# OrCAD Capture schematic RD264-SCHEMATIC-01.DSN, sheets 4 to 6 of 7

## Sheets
4 4: size A3
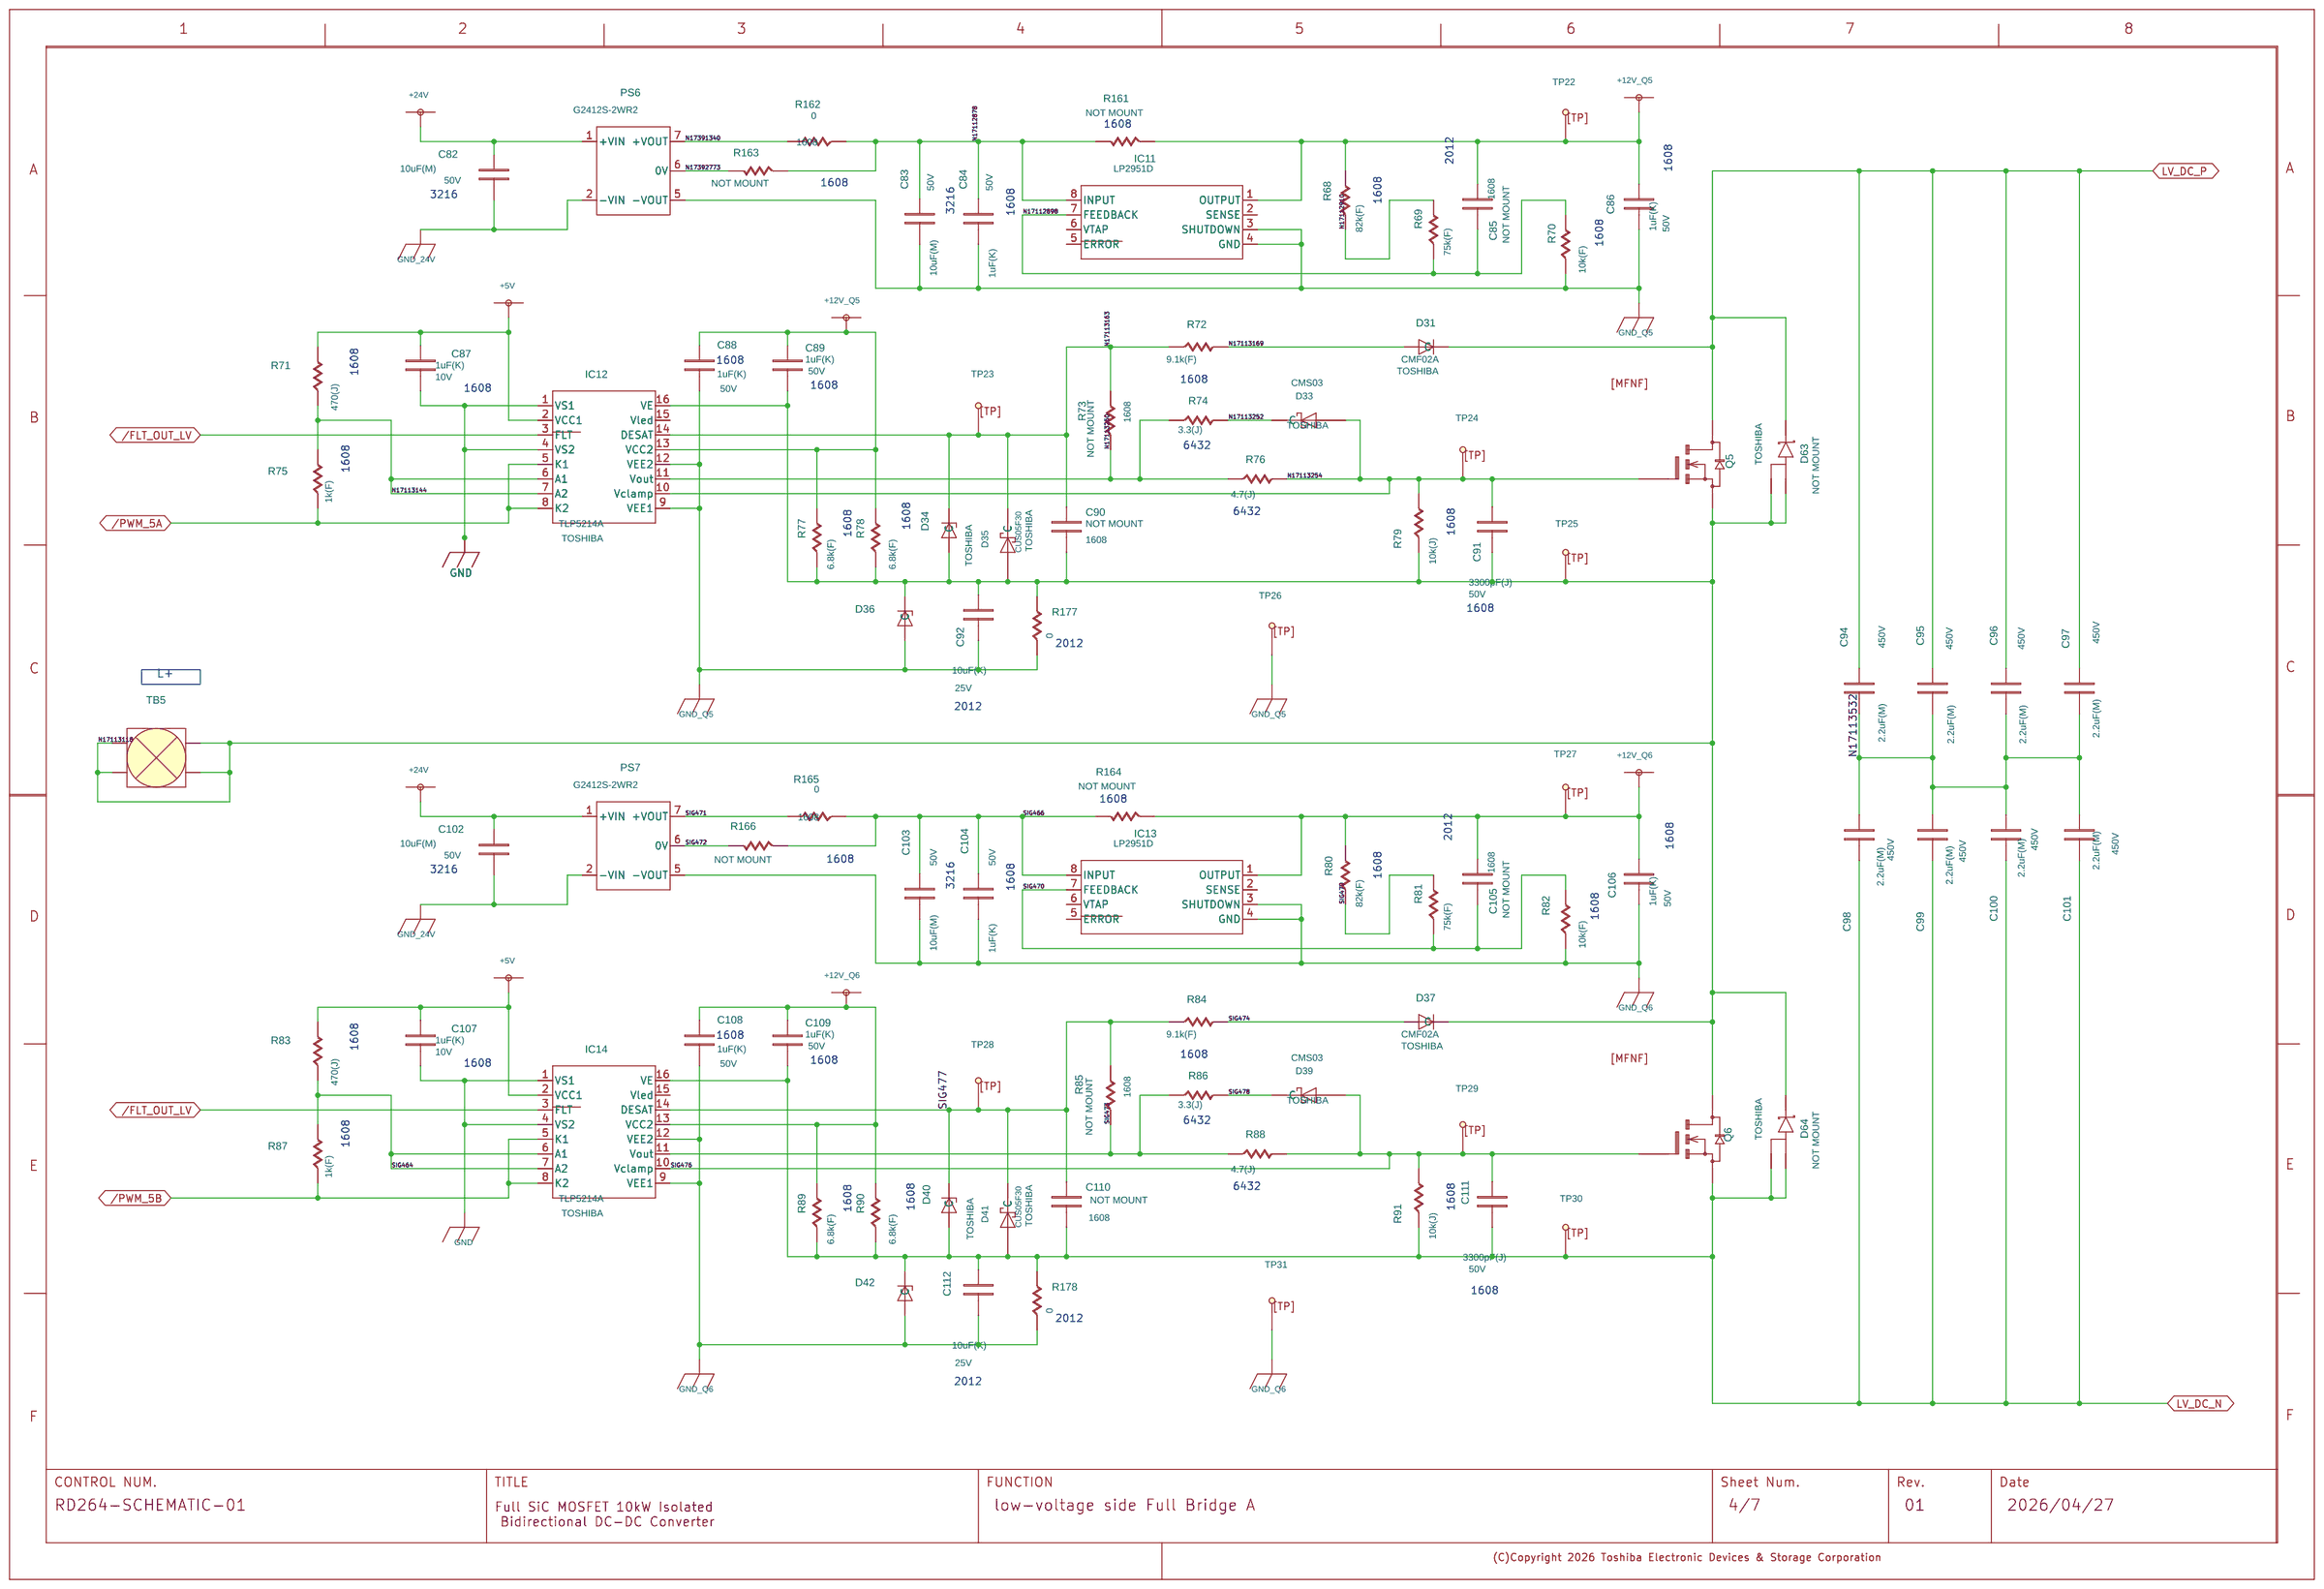
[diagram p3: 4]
5 3: size A3
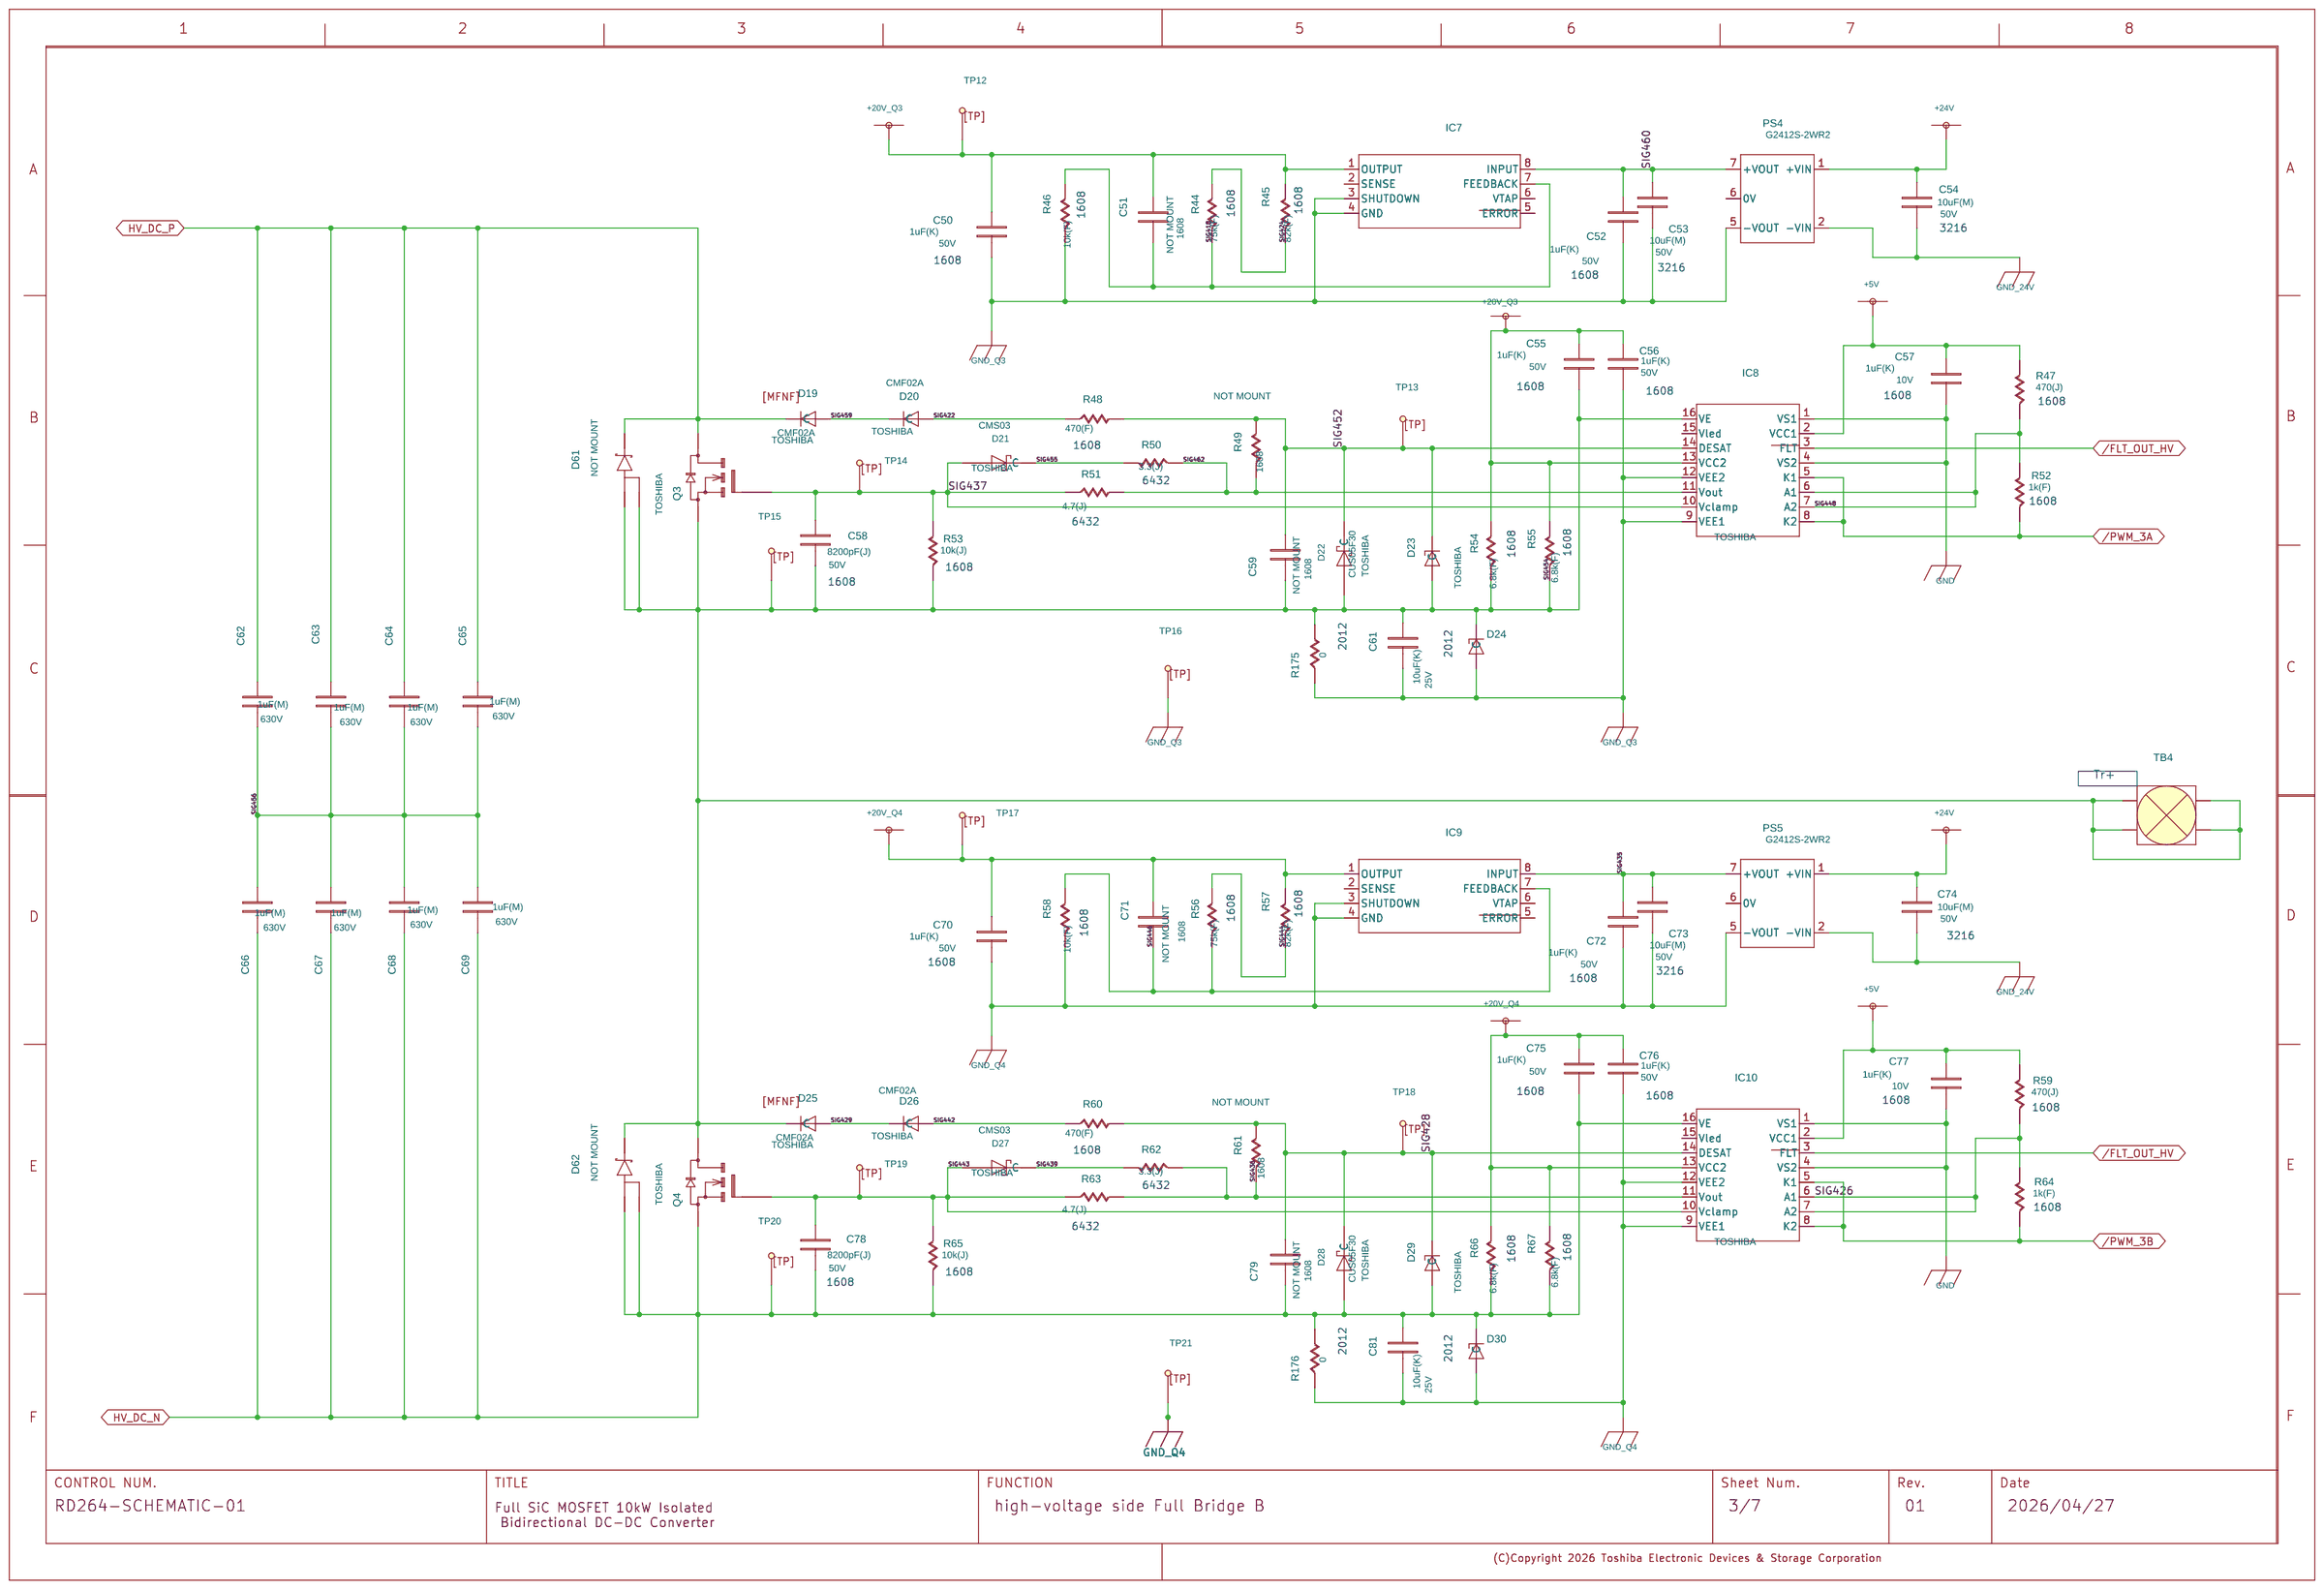
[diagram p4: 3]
6 2: size A3
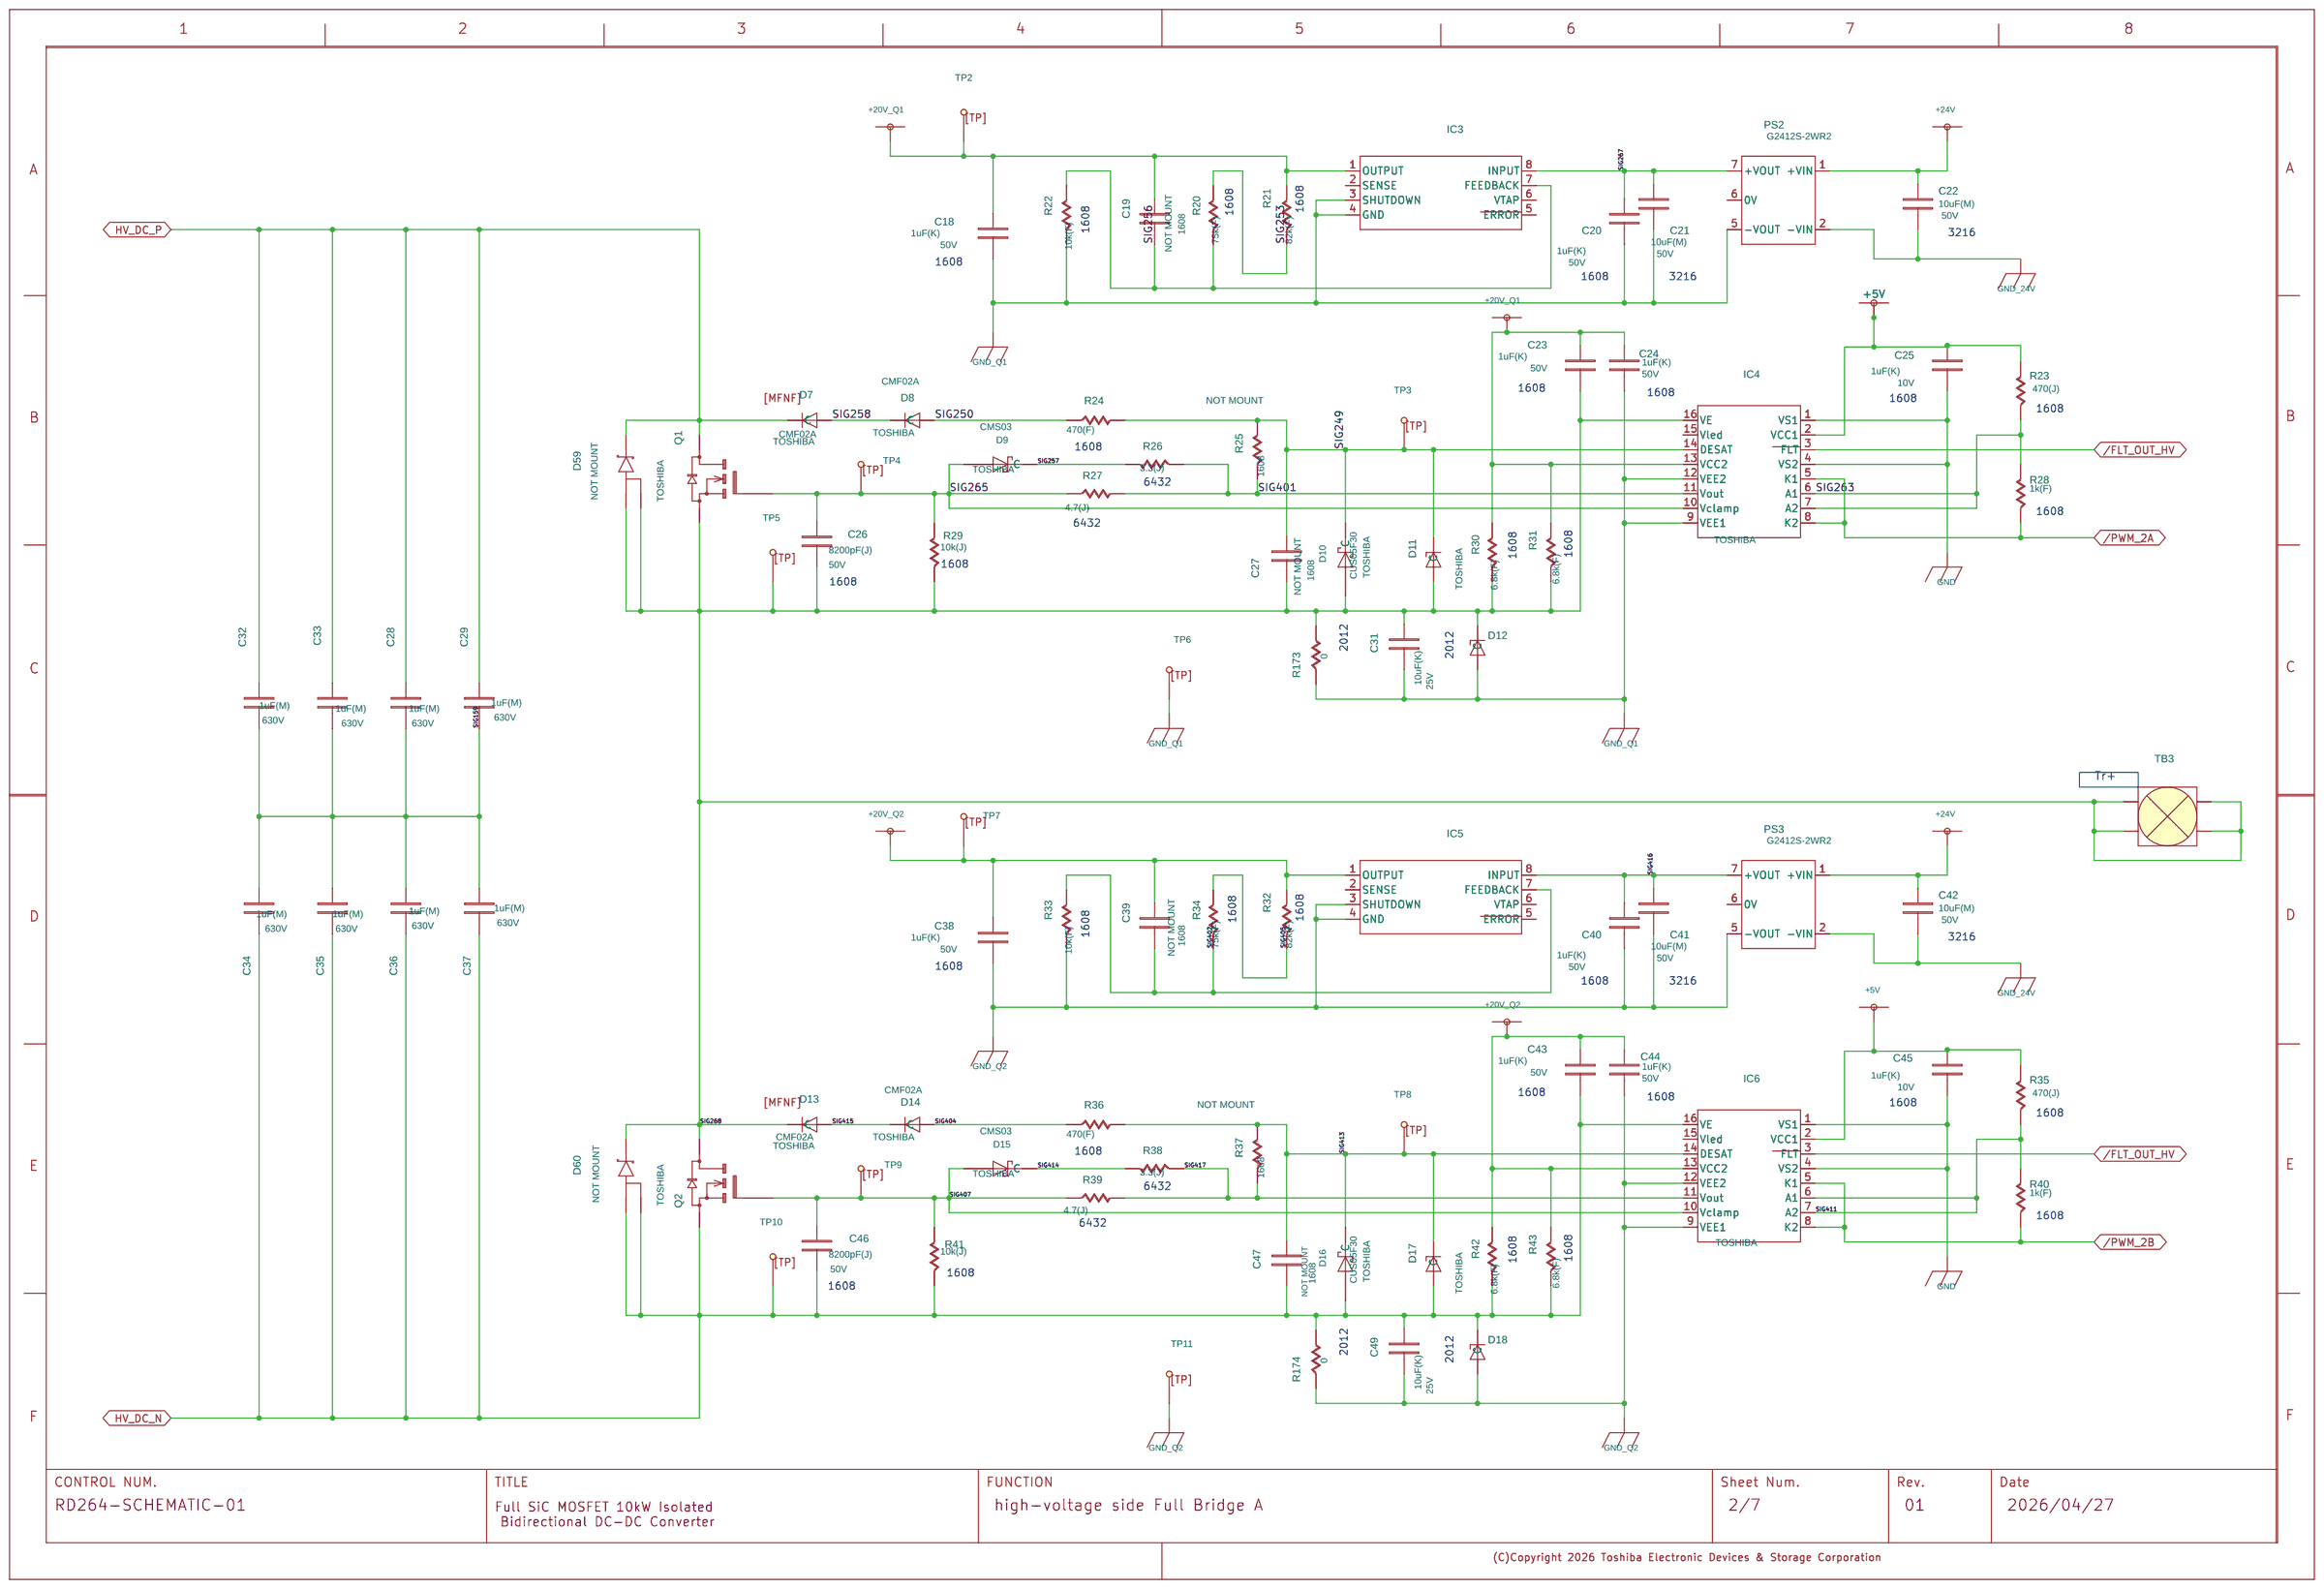
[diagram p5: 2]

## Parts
sheet 2
C18  GRM188R61H105KAALD
C19  NC_C1608
C20  GRM188R61H105KAALD
C21  GRM31CR61H106MA12L
C22  GRM31CR61H106MA12L
C23  GRM188R61H105KAALD
C24  GRM188R61H105KAALD
C25  GRM188R71A105KA61D
C26  GRM1885C1H332JA01D
C27  NC_C1608
C28  CKG57NX7T2J105M500JH
C29  CKG57NX7T2J105M500JH
C31  GRM21BC71E106KE11L
C32  CKG57NX7T2J105M500JH
C33  CKG57NX7T2J105M500JH
C34  CKG57NX7T2J105M500JH
C35  CKG57NX7T2J105M500JH
C36  CKG57NX7T2J105M500JH
C37  CKG57NX7T2J105M500JH
C38  GRM188R61H105KAALD
C39  NC_C1608
C40  GRM188R61H105KAALD
C41  GRM31CR61H106MA12L
C42  GRM31CR61H106MA12L
C43  GRM188R61H105KAALD
C44  GRM188R61H105KAALD
C45  GRM188R71A105KA61D
C46  GRM1885C1H332JA01D
C47  NC_C1608
C49  GRM21BC71E106KE11L
D7  CMF05
D8  CMF05
D9  SBD
D10  SBD
D11  CRY82
D12  KDZVTR2.0B
D13  CMF05
D14  CMF05
D15  SBD
D16  SBD
D17  CRY82
D18  KDZVTR2.0B
D59  NC_TO-247
D60  NC_TO-247
IC3  LP2951D
IC4  TLP5214A
IC5  LP2951D
IC6  TLP5214A
PS2  G2412S-2WR2
PS3  G2412S-2WR2
Q1  TW070J120B
Q2  TW070J120B
R20  RK73H1JTTD7502F
R21  RK73H1JTTD8202F
R22  RK73H1JTTD1002F
R23  RK73B1JTTD471J
R24  ERJ3EKF4700V
R25  NC_R1608
R26  ERJ1TYJ3R3U
R27  ERJ1TYJ4R7U
R28  RK73H1JTTD1001F
R29  RK73B1JTTD103J
R30  RK73H1JTTD6801F
R31  RK73H1JTTD6801F
R32  RK73H1JTTD8202F
R33  RK73H1JTTD1002F
R34  RK73H1JTTD7502F
R35  RK73B1JTTD471J
R36  ERJ3EKF4700V
R37  NC_R1608
R38  ERJ1TYJ3R3U
R39  ERJ1TYJ4R7U
R40  RK73H1JTTD1001F
R41  RK73B1JTTD103J
R42  RK73H1JTTD6801F
R43  RK73H1JTTD6801F
R173  RK73Z2ATTD
R174  RK73Z2ATTD
TB3  OP-057
TP2  TP
TP3  TP
TP4  TP
TP5  TP
TP6  TP
TP7  TP
TP8  TP
TP9  TP
TP10  TP
TP11  TP
U?#5  WAKU_DEF100
sheet 3
C50  GRM188R61H105KAALD
C51  NC_C1608
C52  GRM188R61H105KAALD
C53  GRM31CR61H106MA12L
C54  GRM31CR61H106MA12L
C55  GRM188R61H105KAALD
C56  GRM188R61H105KAALD
C57  GRM188R71A105KA61D
C58  GRM1885C1H332JA01D
C59  NC_C1608
C61  GRM21BC71E106KE11L
C62  CKG57NX7T2J105M500JH
C63  CKG57NX7T2J105M500JH
C64  CKG57NX7T2J105M500JH
C65  CKG57NX7T2J105M500JH
C66  CKG57NX7T2J105M500JH
C67  CKG57NX7T2J105M500JH
C68  CKG57NX7T2J105M500JH
C69  CKG57NX7T2J105M500JH
C70  GRM188R61H105KAALD
C71  NC_C1608
C72  GRM188R61H105KAALD
C73  GRM31CR61H106MA12L
C74  GRM31CR61H106MA12L
C75  GRM188R61H105KAALD
C76  GRM188R61H105KAALD
C77  GRM188R71A105KA61D
C78  GRM1885C1H332JA01D
C79  NC_C1608
C81  GRM21BC71E106KE11L
D19  CMF05
D20  CMF05
D21  SBD
D22  SBD
D23  CRY82
D24  KDZVTR2.0B
D25  CMF05
D26  CMF05
D27  SBD
D28  SBD
D29  CRY82
D30  KDZVTR2.0B
D61  NC_TO-247
D62  NC_TO-247
IC7  LP2951D
IC8  TLP5214A
IC9  LP2951D
IC10  TLP5214A
PS4  G2412S-2WR2
PS5  G2412S-2WR2
Q3  TW070J120B
Q4  TW070J120B
R44  RK73H1JTTD7502F
R45  RK73H1JTTD8202F
R46  RK73H1JTTD1002F
R47  RK73B1JTTD471J
R48  ERJ3EKF4700V
R49  NC_R1608
R50  ERJ1TYJ3R3U
R51  ERJ1TYJ4R7U
R52  RK73H1JTTD1001F
R53  RK73B1JTTD103J
R54  RK73H1JTTD6801F
R55  RK73H1JTTD6801F
R56  RK73H1JTTD7502F
R57  RK73H1JTTD8202F
R58  RK73H1JTTD1002F
R59  RK73B1JTTD471J
R60  ERJ3EKF4700V
R61  NC_R1608
R62  ERJ1TYJ3R3U
R63  ERJ1TYJ4R7U
R64  RK73H1JTTD1001F
R65  RK73B1JTTD103J
R66  RK73H1JTTD6801F
R67  RK73H1JTTD6801F
R175  RK73Z2ATTD
R176  RK73Z2ATTD
TB4  OP-057
TP12  TP
TP13  TP
TP14  TP
TP15  TP
TP16  TP
TP17  TP
TP18  TP
TP19  TP
TP20  TP
TP21  TP
U?#4  WAKU_DEF100
sheet 4
C82  GRM31CR61H106MA12L
C83  GRM31CR61H106MA12L
C84  GRM188R61H105KAALD
C85  NC_C1608
C86  GRM188R61H105KAALD
C87  GRM188R71A105KA61D
C88  GRM188R61H105KAALD
C89  GRM188R61H105KAALD
C90  NC_C1608
C91  GRM1885C1H682JA01D
C92  GRM21BC71E106KE11L
C94  CKG57NX7T2W225M500JH
C95  CKG57NX7T2W225M500JH
C96  CKG57NX7T2W225M500JH
C97  CKG57NX7T2W225M500JH
C98  CKG57NX7T2W225M500JH
C99  CKG57NX7T2W225M500JH
C100  CKG57NX7T2W225M500JH
C101  CKG57NX7T2W225M500JH
C102  GRM31CR61H106MA12L
C103  GRM31CR61H106MA12L
C104  GRM188R61H105KAALD
C105  NC_C1608
C106  GRM188R61H105KAALD
C107  GRM188R71A105KA61D
C108  GRM188R61H105KAALD
C109  GRM188R61H105KAALD
C110  NC_C1608
C111  GRM1885C1H682JA01D
C112  GRM21BC71E106KE11L
D31  CMF05
D33  SBD
D34  CRY82
D35  SBD
D36  KDZVTR2.0B
D37  CMF05
D39  SBD
D40  CRY82
D41  SBD
D42  KDZVTR2.0B
D63  NC_TO-247
D64  NC_TO-247
IC11  LP2951D
IC12  TLP5214A
IC13  LP2951D
IC14  TLP5214A
PS6  G2412S-2WR2
PS7  G2412S-2WR2
Q5  TK49N65W5
Q6  TK49N65W5
R68  RK73H1JTTD8202F
R69  RK73H1JTTD7502F
R70  RK73H1JTTD1002F
R71  RK73B1JTTD471J
R72  ERJ3EKF9101V
R73  NC_R1608
R74  ERJ1TYJ100U
R75  RK73H1JTTD1001F
R76  ERJ1TYJ470U
R77  RK73H1JTTD6801F
R78  RK73H1JTTD6801F
R79  RK73B1JTTD103J
R80  RK73H1JTTD8202F
R81  RK73H1JTTD7502F
R82  RK73H1JTTD1002F
R83  RK73B1JTTD471J
R84  ERJ3EKF9101V
R85  NC_R1608
R86  ERJ1TYJ100U
R87  RK73H1JTTD1001F
R88  ERJ1TYJ470U
R89  RK73H1JTTD6801F
R90  RK73H1JTTD6801F
R91  RK73B1JTTD103J
R161  RK73Z1JTTD
R162  NC_R1608
R163  RK73Z1JTTD
R164  RK73Z1JTTD
R165  NC_R1608
R166  RK73Z1JTTD
R177  RK73Z2ATTD
R178  RK73Z2ATTD
TB5  OP-057
TP22  TP
TP23  TP
TP24  TP
TP25  TP
TP26  TP
TP27  TP
TP28  TP
TP29  TP
TP30  TP
TP31  TP
U?#3  WAKU_DEF100

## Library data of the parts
C18 C38 C50 C70 = C_v2: COMP: C-GRM188R61H105KAALD; COMPONENTNAME: C_C.Normal_package; COMPONENTTYPE: 4; FUNCN: C_C.Normal_package; INSTANCENAME: INS16721371; NOTE: 1uF 50V; PART TYPE: Ceramic Capacitor; REFERENCE TEMPLATE: C; SIZE: 1; VAL1: 1uF(K); VAL2: 50V
C19 C39 C51 C71 = C_v2: COMP: C-1608_NM; COMPONENTNAME: C_C.Normal_package; COMPONENTTYPE: 4; FUNCN: C_C.Normal_package; INSTANCENAME: INS16721315; NOTMOUNT: NOT MOUNT; PART TYPE: Ceramic Capacitor; REFERENCE TEMPLATE: C; SIZE: 1; SIZECODESMD: 1608
C20 C40 C52 C72 = C_v2: COMP: C-GRM188R61H105KAALD; COMPONENTNAME: C_C.Normal_package; COMPONENTTYPE: 4; FUNCN: C_C.Normal_package; INSTANCENAME: INS15595921; NOTE: 1uF 50V; PART TYPE: Ceramic Capacitor; REFERENCE TEMPLATE: C; SIZE: 1; VAL1: 1uF(K); VAL2: 50V
C21 C41 C53 C73 = C_v2: COMP: C-GRM31CR61H106MA12L; COMPONENTNAME: C_C.Normal_package; COMPONENTTYPE: 4; FUNCN: C_C.Normal_package; INSTANCENAME: INS15595987; NOTE: 10uF 50V; PART TYPE: Ceramic Capacitor; REFERENCE TEMPLATE: C; SIZE: 1; VAL1: 10uF(M); VAL2: 50V
C22 C42 C54 C74 = C_v2: COMP: C-GRM31CR61H106MA12L; COMPONENTNAME: C_C.Normal_package; COMPONENTTYPE: 4; FUNCN: C_C.Normal_package; INSTANCENAME: INS15596097; NOTE: 10uF 50V; PART TYPE: Ceramic Capacitor; REFERENCE TEMPLATE: C; SIZE: 1; VAL1: 10uF(M); VAL2: 50V
C23 C43 C55 C75 = C_v2: COMP: C-GRM188R61H105KAALD; COMPONENTNAME: C_C.Normal_package; COMPONENTTYPE: 4; FUNCN: C_C.Normal_package; INSTANCENAME: INS15596075; NOTE: 1uF 50V; PART TYPE: Ceramic Capacitor; REFERENCE TEMPLATE: C; SIZE: 1; VAL1: 1uF(K); VAL2: 50V
C24 C44 C56 C76 = C_v2: COMP: C-GRM188R61H105KAALD; COMPONENTNAME: C_C.Normal_package; COMPONENTTYPE: 4; FUNCN: C_C.Normal_package; INSTANCENAME: INS15596185; NOTE: 1uF 50V; PART TYPE: Ceramic Capacitor; REFERENCE TEMPLATE: C; SIZE: 1; VAL1: 1uF(K); VAL2: 50V
C25 C45 C57 C77 = C_v2: COMP: C-GRM188R71A105KA61D; COMPONENTNAME: C_C.Normal_package; COMPONENTTYPE: 4; FUNCN: C_C.Normal_package; INSTANCENAME: INS15595789; NOTE: 1uF 10V; PART TYPE: Ceramic Capacitor; REFERENCE TEMPLATE: C; SIZE: 1; VAL1: 1uF(K); VAL2: 10V
C26 C46 C58 C78 = C_v2: COMP: C-GRM1885C1H332JA01D; COMPONENTNAME: C_C.Normal_package; COMPONENTTYPE: 4; FUNCN: C_C.Normal_package; INSTANCENAME: INS15595745; NOTE: 3300pF 50V; PART TYPE: Ceramic Capacitor; REFERENCE TEMPLATE: C; SIZE: 1; VAL1: 8200pF(J); VAL2: 50V
C27 C47 C59 C79 = C_v2: COMP: C-1608_NM; COMPONENTNAME: C_C.Normal_package; COMPONENTTYPE: 4; FUNCN: C_C.Normal_package; INSTANCENAME: INS15596281; NOTMOUNT: NOT MOUNT; PART TYPE: Ceramic Capacitor; REFERENCE TEMPLATE: C; SIZE: 1; SIZECODESMD: 1608
C28 C64 = C_v2: COMP: C-CKG57NX7T2J105M500JH; COMPONENTNAME: C_C.Normal_package; COMPONENTTYPE: 4; FUNCN: C_C.Normal_package; INSTANCENAME: INS15645445; NOTE: 1uF 650V; PART TYPE: Ceramic Capacitor; REFERENCE TEMPLATE: C; SIZE: 1; VAL1: 1uF(M); VAL2: 630V
C29 C65 = C_v2: COMP: C-CKG57NX7T2J105M500JH; COMPONENTNAME: C_C.Normal_package; COMPONENTTYPE: 4; FUNCN: C_C.Normal_package; INSTANCENAME: INS15645292; NOTE: 1uF 650V; PART TYPE: Ceramic Capacitor; REFERENCE TEMPLATE: C; SIZE: 1; VAL1: 1uF(M); VAL2: 630V
C31 C49 C61 C81 = C_v2: COMP: C-GRM21BC71E106KE11L; COMPONENTNAME: C_C.Normal_package; COMPONENTTYPE: 4; FUNCN: C_C.Normal_package; INSTANCENAME: INS17875665; NOTE: 10uF 25V; PART TYPE: Ceramic Capacitor; REFERENCE TEMPLATE: C; SIZE: 1; VAL1: 10uF(K); VAL2: 25V
C32 C62 = C_v2: COMP: C-CKG57NX7T2J105M500JH; COMPONENTNAME: C_C.Normal_package; COMPONENTTYPE: 4; FUNCN: C_C.Normal_package; INSTANCENAME: INS15645741; NOTE: 1uF 650V; PART TYPE: Ceramic Capacitor; REFERENCE TEMPLATE: C; SIZE: 1; VAL1: 1uF(M); VAL2: 630V
C33 C63 = C_v2: COMP: C-CKG57NX7T2J105M500JH; COMPONENTNAME: C_C.Normal_package; COMPONENTTYPE: 4; FUNCN: C_C.Normal_package; INSTANCENAME: INS15645594; NOTE: 1uF 650V; PART TYPE: Ceramic Capacitor; REFERENCE TEMPLATE: C; SIZE: 1; VAL1: 1uF(M); VAL2: 630V
C34 C66 = C_v2: COMP: C-CKG57NX7T2J105M500JH; COMPONENTNAME: C_C.Normal_package; COMPONENTTYPE: 4; FUNCN: C_C.Normal_package; INSTANCENAME: INS15646846; NOTE: 1uF 650V; PART TYPE: Ceramic Capacitor; REFERENCE TEMPLATE: C; SIZE: 1; VAL1: 1uF(M); VAL2: 630V
C35 C67 = C_v2: COMP: C-CKG57NX7T2J105M500JH; COMPONENTNAME: C_C.Normal_package; COMPONENTTYPE: 4; FUNCN: C_C.Normal_package; INSTANCENAME: INS15646830; NOTE: 1uF 650V; PART TYPE: Ceramic Capacitor; REFERENCE TEMPLATE: C; SIZE: 1; VAL1: 1uF(M); VAL2: 630V
C36 C68 = C_v2: COMP: C-CKG57NX7T2J105M500JH; COMPONENTNAME: C_C.Normal_package; COMPONENTTYPE: 4; FUNCN: C_C.Normal_package; INSTANCENAME: INS15646814; NOTE: 1uF 650V; PART TYPE: Ceramic Capacitor; REFERENCE TEMPLATE: C; SIZE: 1; VAL1: 1uF(M); VAL2: 630V
C37 C69 = C_v2: COMP: C-CKG57NX7T2J105M500JH; COMPONENTNAME: C_C.Normal_package; COMPONENTTYPE: 4; FUNCN: C_C.Normal_package; INSTANCENAME: INS15646798; NOTE: 1uF 650V; PART TYPE: Ceramic Capacitor; REFERENCE TEMPLATE: C; SIZE: 1; VAL1: 1uF(M); VAL2: 630V
D7 D13 D19 D25 = D: COMP: D-CMF05; COMPONENTNAME: D_D.Normal_package; COMPONENTTYPE: 4; FUNCN: D_D.Normal_package; INSTANCENAME: INS15634007; USERCOMPTEXT3: TOSHIBA; VAL3: CMF02A
D8 D14 D20 D26 = D: COMP: D-CMF05; COMPONENTNAME: D_D.Normal_package; COMPONENTTYPE: 4; FUNCN: D_D.Normal_package; INSTANCENAME: INS17062002; USERCOMPTEXT3: TOSHIBA; VAL3: CMF02A
D9 D15 D21 D27 D33 D39 = SBD: COMP: CMS03; COMPONENTTYPE: 4; USERCOMPTEXT3: TOSHIBA; VAL3: CMS03
D10 D16 D22 D28 D35 D41 = SBD: COMP: CUS05F30; COMPONENTTYPE: 4; USERCOMPTEXT3: TOSHIBA; VAL3: CUS05F30
D11 D17 D23 D29 = ZD: COMP: D-CRY82; COMPONENTNAME: ZD_ZD.Normal_package; COMPONENTTYPE: 4; FUNCN: ZD_ZD.Normal_package; INSTANCENAME: INS15635127; USERCOMPTEXT3: TOSHIBA
D12 D18 D24 D30 = ZD: COMP: D-KDZVTR2.0B; COMPONENTNAME: ZD_ZD.Normal_package; COMPONENTTYPE: 4; FUNCN: ZD_ZD.Normal_package; INSTANCENAME: INS15595549; PART TYPE: Zener diode; REFERENCE TEMPLATE: D
D59-D62 = NC_TO_247: COMP: D-TO-247_NM; COMPONENTNAME: NC_TO-247_NC_TO-247.Normal_package; COMPONENTTYPE: 4; FUNCN: NC_TO-247_NC_TO-247.Normal_package; INSTANCENAME: INS17322041; NOTMOUNT: NOT MOUNT; SAVECOUNT: 1; UPDATEDATE: 2020/05/13; UPDATETIME: 14:31:25
IC3 IC5 IC7 IC9 = LP2951D: COMP: IC-LP2951D; COMPONENTTYPE: 4
IC4 IC6 IC8 IC10 IC12 IC14 = TLP5214A: COMP: IC-TLP5214A; COMPONENTTYPE: 4; USERCOMPTEXT3: TOSHIBA
PS2-PS7 = G2412S_2WR2: COMP: PS-G2412S-2WR2; COMPONENTTYPE: 4
Q1-Q4 = MFNF: COMP: TW060N120C; COMPONENTNAME: MFNF_MFNF.Normal_package; COMPONENTTYPE: 4; FUNCN: MFNF_MFNF.Normal_package; INSTANCENAME: INS15597005; USERCOMPTEXT3: TOSHIBA; VAL3: TW060N120C
R20 R34 R44 R56 = R: COMP: R-RK73H1JTTD7502F; COMPONENTNAME: R_R.Normal_package; COMPONENTTYPE: 4; FUNCN: R_R.Normal_package; INSTANCENAME: INS16721339; NOTE: 75kohm 0.1W; VAL1: 75k(F); VAL2: 100mw
R21 R32 R45 R57 = R: COMP: R-RK73H1JTTD8202F; COMPONENTNAME: R_R.Normal_package; COMPONENTTYPE: 4; FUNCN: R_R.Normal_package; INSTANCENAME: INS16721291; NOTE: 82kohm 0.1W; VAL1: 82k(F); VAL2: 100mw
R22 R33 R46 R58 = R: COMP: R-RK73H1JTTD1002F; COMPONENTNAME: R_R.Normal_package; COMPONENTTYPE: 4; FUNCN: R_R.Normal_package; INSTANCENAME: INS16721355; NOTE: 10kohm 0.1W; VAL1: 10k(F); VAL2: 100mw
R23 R35 R47 R59 = R: COMP: R-RK73B1JTTD471J; COMPONENTNAME: R_R.Normal_package; COMPONENTTYPE: 4; FUNCN: R_R.Normal_package; INSTANCENAME: INS15595899; NOTE: 470ohm 0.1W; PART TYPE: Resistor SMD; SIZE: 1; VAL1: 470(J); VAL2: 125mw
R24 R36 R48 R60 = R: COMP: R-ERJ3EKF4700V; COMPONENTNAME: R_R.Normal_package; COMPONENTTYPE: 4; FUNCN: R_R.Normal_package; INSTANCENAME: INS17252639; NOTE: 470ohm 0.1W; PART TYPE: Resistor SMD; SIZE: 1; VAL1: 470(F); VAL2: 100mw
R25 R37 R49 R61 = R: COMP: R-1608_NM; COMPONENTNAME: R_R.Normal_package; COMPONENTTYPE: 4; FUNCN: R_R.Normal_package; INSTANCENAME: INS15655219; NOTMOUNT: NOT MOUNT; PART TYPE: Resistor SMD; SIZE: 1; SIZECODESMD: 1608
R26 R38 R50 R62 = R: COMP: R-ERJ1TYJ3R3U; COMPONENTNAME: R_R.Normal_package; COMPONENTTYPE: 4; FUNCN: R_R.Normal_package; INSTANCENAME: INS15655235; NOTE: 3.3ohm 1W; PART TYPE: Resistor SMD; SIZE: 1; VAL1: 3.3(J); VAL2: 1w
R27 R39 R51 R63 = R: COMP: R-ERJ1TYJ4R7U; COMPONENTNAME: R_R.Normal_package; COMPONENTTYPE: 4; FUNCN: R_R.Normal_package; INSTANCENAME: INS17252727; NOTE: 4.7ohm 1W; PART NUMBER: TMP-430; PART TYPE: Resistor SMD; VAL1: 4.7(J); VAL2: 1w
R28 R40 R52 R64 = R: COMP: R-RK73H1JTTD1001F; COMPONENTNAME: R_R.Normal_package; COMPONENTTYPE: 4; FUNCN: R_R.Normal_package; INSTANCENAME: INS15596711; NOTE: 1.0kohm 0.1W; PART TYPE: Resistor SMD; SIZE: 1; VAL1: 1k(F); VAL2: 125mw
R29 R41 R53 R65 = R: COMP: R-RK73B1JTTD103J; COMPONENTNAME: R_R.Normal_package; COMPONENTTYPE: 4; FUNCN: R_R.Normal_package; INSTANCENAME: INS15595811; NOTE: 10kohm 0.1W; PART TYPE: Resistor SMD; SIZE: 1; VAL1: 10k(J); VAL2: 100mw
R30 R42 R54 R66 = R: COMP: R-RK73H1JTTD6801F; COMPONENTNAME: R_R.Normal_package; COMPONENTTYPE: 4; FUNCN: R_R.Normal_package; INSTANCENAME: INS15596689; NOTE: 6.8kohm 0.1W; PART TYPE: Resistor SMD; SIZE: 1; VAL1: 6.8k(F); VAL2: 100mw
R31 R43 R55 R67 = R: COMP: R-RK73H1JTTD6801F; COMPONENTNAME: R_R.Normal_package; COMPONENTTYPE: 4; FUNCN: R_R.Normal_package; INSTANCENAME: INS15596877; NOTE: 6.8kohm 0.1W; PART TYPE: Resistor SMD; SIZE: 1; VAL1: 6.8k(F); VAL2: 100mw
R173-R176 = R: COMP: R-RK73Z2ATTD; COMPONENTNAME: R_R.Normal_package; COMPONENTTYPE: 4; FUNCN: R_R.Normal_package; INSTANCENAME: INS17875194; NOTE: 0ohm 0.25w; PART TYPE: Resistor SMD; SIZE: 1; VAL1: 0
TB3 TB4 = OP_057: COMP: TB-OP-057; COMPONENTNAME: OP-057_OP-057.Normal_package; COMPONENTTYPE: 4; FUNCN: OP-057_OP-057.Normal_package; INSTANCENAME: INS17363781; PART NUMBER: TMP-784; PART TYPE: Terminal Block; REFERENCE TEMPLATE: TB; SAVECOUNT: 1; UPDATETIME: 14:31:25
TP2-TP31 = TP: COMP: TP-HK-3-G; COMPONENTTYPE: 4; VAL3: HK-3-G
U?#5 = WAKU_DEF100: COMPONENTTYPE: 2; DATE: 2026/04/27; DRAWINGNUMBER: RD264-SCHEMATIC-01; FUNCTION: high-voltage side Full Bridge A; REVISION: 01; SHEETNUMBER: 2/7; SHTSAVECOUNT: 17; TITLE: Full SiC MOSFET 10kW Isolated / Bidirectional DC-DC Converter; UPDATEDATE: 2026.4.27; UPDATETIME: 14:22:33
U?#4 = WAKU_DEF100: COMPONENTTYPE: 2; DATE: 2026/04/27; DRAWINGNUMBER: RD264-SCHEMATIC-01; FUNCTION: high-voltage side Full Bridge B; REVISION: 01; SHEETNUMBER: 3/7; SHTSAVECOUNT: 16; TITLE: Full SiC MOSFET 10kW Isolated / Bidirectional DC-DC Converter; UPDATEDATE: 2026.4.27; UPDATETIME: 14:22:34
C82 C102 = C_v2: COMP: C-GRM31CR61H106MA12L; COMPONENTNAME: C_C.Normal_package; COMPONENTTYPE: 4; FUNCN: C_C.Normal_package; INSTANCENAME: INS17112921; NOTE: 10uF 50V; PART TYPE: Ceramic Capacitor; REFERENCE TEMPLATE: C; SIZE: 1; VAL1: 10uF(M); VAL2: 50V
C83 C103 = C_v2: COMP: C-GRM31CR61H106MA12L; COMPONENTNAME: C_C.Normal_package; COMPONENTTYPE: 4; FUNCN: C_C.Normal_package; INSTANCENAME: INS17112929; NOTE: 10uF 50V; PART TYPE: Ceramic Capacitor; REFERENCE TEMPLATE: C; SIZE: 1; VAL1: 10uF(M); VAL2: 50V
C84 C104 = C_v2: COMP: C-GRM188R61H105KAALD; COMPONENTNAME: C_C.Normal_package; COMPONENTTYPE: 4; FUNCN: C_C.Normal_package; INSTANCENAME: INS17112937; NOTE: 1uF 50V; PART TYPE: Ceramic Capacitor; REFERENCE TEMPLATE: C; SIZE: 1; VAL1: 1uF(K); VAL2: 50V
C85 C105 = C_v2: COMP: C-1608_NM; COMPONENTNAME: C_C.Normal_package; COMPONENTTYPE: 4; FUNCN: C_C.Normal_package; INSTANCENAME: INS17112913; NOTMOUNT: NOT MOUNT; PART TYPE: Ceramic Capacitor; REFERENCE TEMPLATE: C; SIZE: 1; SIZECODESMD: 1608
C86 C106 = C_v2: COMP: C-GRM188R61H105KAALD; COMPONENTNAME: C_C.Normal_package; COMPONENTTYPE: 4; FUNCN: C_C.Normal_package; INSTANCENAME: INS17112961; NOTE: 1uF 50V; PART TYPE: Ceramic Capacitor; REFERENCE TEMPLATE: C; SIZE: 1; VAL1: 1uF(K); VAL2: 50V
C87 C107 = C_v2: COMP: C-GRM188R71A105KA61D; COMPONENTNAME: C_C.Normal_package; COMPONENTTYPE: 4; FUNCN: C_C.Normal_package; INSTANCENAME: INS17113085; NOTE: 1uF 10V; PART TYPE: Ceramic Capacitor; REFERENCE TEMPLATE: C; SIZE: 1; VAL1: 1uF(K); VAL2: 10V
C88 C108 = C_v2: COMP: C-GRM188R61H105KAALD; COMPONENTNAME: C_C.Normal_package; COMPONENTTYPE: 4; FUNCN: C_C.Normal_package; INSTANCENAME: INS17113061; NOTE: 1uF 50V; PART TYPE: Ceramic Capacitor; REFERENCE TEMPLATE: C; SIZE: 1; VAL1: 1uF(K); VAL2: 50V
C89 C109 = C_v2: COMP: C-GRM188R61H105KAALD; COMPONENTNAME: C_C.Normal_package; COMPONENTTYPE: 4; FUNCN: C_C.Normal_package; INSTANCENAME: INS17113069; NOTE: 1uF 50V; PART TYPE: Ceramic Capacitor; REFERENCE TEMPLATE: C; SIZE: 1; VAL1: 1uF(K); VAL2: 50V
C90 C110 = C_v2: COMP: C-1608_NM; COMPONENTNAME: C_C.Normal_package; COMPONENTTYPE: 4; FUNCN: C_C.Normal_package; INSTANCENAME: INS17113388; NOTMOUNT: NOT MOUNT; PART TYPE: Ceramic Capacitor; REFERENCE TEMPLATE: C; SIZE: 1; SIZECODESMD: 1608
C91 C111 = C_v2: COMP: C-GRM1885C1H682JA01D; COMPONENTNAME: C_C.Normal_package; COMPONENTTYPE: 4; FUNCN: C_C.Normal_package; INSTANCENAME: INS17753463; NOTE: 6800pF 50V; PART TYPE: Ceramic Capacitor; REFERENCE TEMPLATE: C; SIZE: 1; VAL1: 3300pF(J); VAL2: 50V
C92 C112 = C_v2: COMP: C-GRM21BC71E106KE11L; COMPONENTNAME: C_C.Normal_package; COMPONENTTYPE: 4; FUNCN: C_C.Normal_package; INSTANCENAME: INS17895207; NOTE: 10uF 25V; PART TYPE: Ceramic Capacitor; REFERENCE TEMPLATE: C; SIZE: 1; VAL1: 10uF(K); VAL2: 25V
C94 = C_v2: COMP: C-CKG57NX7T2W225M500JH; COMPONENTNAME: C_C.Normal_package; COMPONENTTYPE: 4; FUNCN: C_C.Normal_package; INSTANCENAME: INS17255321; NOTE: 2.2uF 450V; PART TYPE: Ceramic Capacitor; REFERENCE TEMPLATE: C; SIZE: 1; VAL1: 2.2uF(M); VAL2: 450V
C95 = C_v2: COMP: C-CKG57NX7T2W225M500JH; COMPONENTNAME: C_C.Normal_package; COMPONENTTYPE: 4; FUNCN: C_C.Normal_package; INSTANCENAME: INS17255582; NOTE: 2.2uF 450V; PART TYPE: Ceramic Capacitor; REFERENCE TEMPLATE: C; SIZE: 1; VAL1: 2.2uF(M); VAL2: 450V
C96 = C_v2: COMP: C-CKG57NX7T2W225M500JH; COMPONENTNAME: C_C.Normal_package; COMPONENTTYPE: 4; FUNCN: C_C.Normal_package; INSTANCENAME: INS17255645; NOTE: 2.2uF 450V; PART TYPE: Ceramic Capacitor; REFERENCE TEMPLATE: C; SIZE: 1; VAL1: 2.2uF(M); VAL2: 450V
C97 = C_v2: COMP: C-CKG57NX7T2W225M500JH; COMPONENTNAME: C_C.Normal_package; COMPONENTTYPE: 4; FUNCN: C_C.Normal_package; INSTANCENAME: INS17255762; NOTE: 2.2uF 450V; PART TYPE: Ceramic Capacitor; REFERENCE TEMPLATE: C; SIZE: 1; VAL1: 2.2uF(M); VAL2: 450V
C98 = C_v2: COMP: C-CKG57NX7T2W225M500JH; COMPONENTNAME: C_C.Normal_package; COMPONENTTYPE: 4; FUNCN: C_C.Normal_package; INSTANCENAME: INS17255916; NOTE: 2.2uF 450V; PART TYPE: Ceramic Capacitor; REFERENCE TEMPLATE: C; SIZE: 1; VAL1: 2.2uF(M); VAL2: 450V
C99 = C_v2: COMP: C-CKG57NX7T2W225M500JH; COMPONENTNAME: C_C.Normal_package; COMPONENTTYPE: 4; FUNCN: C_C.Normal_package; INSTANCENAME: INS17256105; NOTE: 2.2uF 450V; PART TYPE: Ceramic Capacitor; REFERENCE TEMPLATE: C; SIZE: 1; VAL1: 2.2uF(M); VAL2: 450V
C100 = C_v2: COMP: C-CKG57NX7T2W225M500JH; COMPONENTNAME: C_C.Normal_package; COMPONENTTYPE: 4; FUNCN: C_C.Normal_package; INSTANCENAME: INS17256431; NOTE: 2.2uF 450V; PART TYPE: Ceramic Capacitor; REFERENCE TEMPLATE: C; SIZE: 1; VAL1: 2.2uF(M); VAL2: 450V
C101 = C_v2: COMP: C-CKG57NX7T2W225M500JH; COMPONENTNAME: C_C.Normal_package; COMPONENTTYPE: 4; FUNCN: C_C.Normal_package; INSTANCENAME: INS17256618; NOTE: 2.2uF 450V; PART TYPE: Ceramic Capacitor; REFERENCE TEMPLATE: C; SIZE: 1; VAL1: 2.2uF(M); VAL2: 450V
D31 D37 = D: COMP: D-CMF05; COMPONENTNAME: D_D.Normal_package; COMPONENTTYPE: 4; FUNCN: D_D.Normal_package; INSTANCENAME: INS17279788; USERCOMPTEXT3: TOSHIBA; VAL3: CMF02A
D34 D40 = ZD: COMP: D-CRY82; COMPONENTNAME: ZD_ZD.Normal_package; COMPONENTTYPE: 4; FUNCN: ZD_ZD.Normal_package; INSTANCENAME: INS17317417; USERCOMPTEXT3: TOSHIBA
D36 D42 = ZD: COMP: D-KDZVTR2.0B; COMPONENTNAME: ZD_ZD.Normal_package; COMPONENTTYPE: 4; FUNCN: ZD_ZD.Normal_package; INSTANCENAME: INS17385836; PART TYPE: Zener diode; REFERENCE TEMPLATE: D
D63 D64 = NC_TO_247: COMP: D-TO-247_NM; COMPONENTNAME: NC_TO-247_NC_TO-247.Normal_package; COMPONENTTYPE: 4; FUNCN: NC_TO-247_NC_TO-247.Normal_package; INSTANCENAME: INS17322987; NOTMOUNT: NOT MOUNT; SAVECOUNT: 1; UPDATEDATE: 2020/05/13; UPDATETIME: 14:31:25; VAL3: TO-247
IC11 IC13 = LP2951D: COMP: IC-LP2951D_NM; COMPONENTTYPE: 4; NOTMOUNT: MOUNT
Q5 Q6 = MFNF: COMP: TW048N65C; COMPONENTNAME: MFNF_MFNF.Normal_package; COMPONENTTYPE: 4; FUNCN: MFNF_MFNF.Normal_package; INSTANCENAME: INS17254361; PART NUMBER: TMP-432; PART TYPE: N-channel  Si power MOSFET; REFERENCE TEMPLATE: Q; USERCOMPTEXT3: TOSHIBA; VAL3: TW048N65C
R68 R80 = R: COMP: R-RK73H1JTTD8202F; COMPONENTNAME: R_R.Normal_package; COMPONENTTYPE: 4; FUNCN: R_R.Normal_package; INSTANCENAME: INS17112901; NOTE: 82kohm 0.1W; VAL1: 82k(F); VAL2: 100mw
R69 R81 = R: COMP: R-RK73H1JTTD7502F; COMPONENTNAME: R_R.Normal_package; COMPONENTTYPE: 4; FUNCN: R_R.Normal_package; INSTANCENAME: INS17112949; NOTE: 75kohm 0.1W; VAL1: 75k(F); VAL2: 100mw
R70 R82 = R: COMP: R-RK73H1JTTD1002F; COMPONENTNAME: R_R.Normal_package; COMPONENTTYPE: 4; FUNCN: R_R.Normal_package; INSTANCENAME: INS17112973; NOTE: 10kohm 0.1W; VAL1: 10k(F); VAL2: 100mw
R71 R83 = R: COMP: R-RK73B1JTTD471J; COMPONENTNAME: R_R.Normal_package; COMPONENTTYPE: 4; FUNCN: R_R.Normal_package; INSTANCENAME: INS17113077; NOTE: 470ohm 0.1W; PART TYPE: Resistor SMD; SIZE: 1; VAL1: 470(J); VAL2: 125mw
R72 R84 = R: COMP: R-ERJ3EKF9101V; COMPONENTNAME: R_R.Normal_package; COMPONENTTYPE: 4; FUNCN: R_R.Normal_package; INSTANCENAME: INS17253791; NOTE: 9.1kohm 0.1W; PART NUMBER: TMP-429; PART TYPE: Resistor SMD; VAL1: 9.1k(F); VAL2: 100mw
R73 R85 = R: COMP: R-1608_NM; COMPONENTNAME: R_R.Normal_package; COMPONENTTYPE: 4; FUNCN: R_R.Normal_package; INSTANCENAME: INS17113188; NOTMOUNT: NOT MOUNT; PART TYPE: Resistor SMD; SIZE: 1; SIZECODESMD: 1608
R74 R86 = R: COMP: R-ERJ1TYJ100U; COMPONENTNAME: R_R.Normal_package; COMPONENTTYPE: 4; FUNCN: R_R.Normal_package; INSTANCENAME: INS17253884; NOTE: 10ohm 1W; PART TYPE: Resistor SMD; SIZE: 1; VAL1: 3.3(J); VAL2: 1w
R75 R87 = R: COMP: R-RK73H1JTTD1001F; COMPONENTNAME: R_R.Normal_package; COMPONENTTYPE: 4; FUNCN: R_R.Normal_package; INSTANCENAME: INS17113262; NOTE: 1.0kohm 0.1W; PART TYPE: Resistor SMD; SIZE: 1; VAL1: 1k(F); VAL2: 125mw
R76 R88 = R: COMP: R-ERJ1TYJ470U; COMPONENTNAME: R_R.Normal_package; COMPONENTTYPE: 4; FUNCN: R_R.Normal_package; INSTANCENAME: INS17753183; NOTE: 47ohm 1W; PART NUMBER: TMP-902; PART TYPE: Resistor SMD; VAL1: 4.7(J); VAL2: 1w
R77 R89 = R: COMP: R-RK73H1JTTD6801F; COMPONENTNAME: R_R.Normal_package; COMPONENTTYPE: 4; FUNCN: R_R.Normal_package; INSTANCENAME: INS17113356; NOTE: 6.8kohm 0.1W; PART TYPE: Resistor SMD; SIZE: 1; VAL1: 6.8k(F); VAL2: 100mw
R78 R90 = R: COMP: R-RK73H1JTTD6801F; COMPONENTNAME: R_R.Normal_package; COMPONENTTYPE: 4; FUNCN: R_R.Normal_package; INSTANCENAME: INS17113364; NOTE: 6.8kohm 0.1W; PART TYPE: Resistor SMD; SIZE: 1; VAL1: 6.8k(F); VAL2: 100mw
R79 R91 = R: COMP: R-RK73B1JTTD103J; COMPONENTNAME: R_R.Normal_package; COMPONENTTYPE: 4; FUNCN: R_R.Normal_package; INSTANCENAME: INS17113334; NOTE: 10kohm 0.1W; PART TYPE: Resistor SMD; SIZE: 1; VAL1: 10k(J); VAL2: 100mw
R161 R164 = R: COMP: R-RK73Z1JTTD; COMPONENTNAME: R_R.Normal_package; COMPONENTTYPE: 4; FUNCN: R_R.Normal_package; INSTANCENAME: INS17390327; NOTE: 0ohm 0.1W; NOTMOUNT: NOT MOUNT; PART TYPE: Resistor SMD; SIZE: 1
R162 R165 = R: COMP: R-1608_NM; COMPONENTNAME: R_R.Normal_package; COMPONENTTYPE: 4; FUNCN: R_R.Normal_package; INSTANCENAME: INS17391865; NOTMOUNT: MOUNT; PART TYPE: Resistor SMD; SIZE: 1; SIZECODESMD: 1608; VAL1: 0
R163 R166 = R: COMP: R-RK73Z1JTTD; COMPONENTNAME: R_R.Normal_package; COMPONENTTYPE: 4; FUNCN: R_R.Normal_package; INSTANCENAME: INS17391891; NOTE: 0ohm 0.1W; NOTMOUNT: NOT MOUNT; PART TYPE: Resistor SMD; SIZE: 1
R177 R178 = R: COMP: R-RK73Z2ATTD; COMPONENTNAME: R_R.Normal_package; COMPONENTTYPE: 4; FUNCN: R_R.Normal_package; INSTANCENAME: INS17894887; NOTE: 0ohm 0.25w; PART TYPE: Resistor SMD; SIZE: 1; VAL1: 0
TB5 = OP_057: COMP: TB-OP-057; COMPONENTNAME: OP-057_OP-057.Normal_package; COMPONENTTYPE: 4; FUNCN: OP-057_OP-057.Normal_package; INSTANCENAME: INS17364097; PART NUMBER: TMP-784; PART TYPE: Terminal Block; REFERENCE TEMPLATE: TB; SAVECOUNT: 1; UPDATETIME: 14:31:25
U?#3 = WAKU_DEF100: COMPONENTTYPE: 2; DATE: 2026/04/27; DRAWINGNUMBER: RD264-SCHEMATIC-01; FUNCTION: low-voltage side Full Bridge A; REVISION: 01; SHEETNUMBER: 4/7; SHTSAVECOUNT: 18; TITLE: Full SiC MOSFET 10kW Isolated / Bidirectional DC-DC Converter; UPDATEDATE: 2026.4.27; UPDATETIME: 14:22:34

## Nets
+5V: C25.1 C45.1 C57.1 C77.1 C87.1 C107.1 IC4.2(VCC1) IC6.2(VCC1) IC8.2(VCC1) IC10.2(VCC1) IC12.2(VCC1) IC14.2(VCC1) R23.1 R35.1 R47.1 R59.1 R71.1 R83.1 ; also on sheet 1 2 3 7
+12V_Q5: C85.1 C86.1 C88.1 C89.1 IC11.1(OUTPUT) IC12.13(VCC2) R68.1 R77.1 R78.1 R161.2 TP22.1
+12V_Q6: C105.1 C106.1 C108.1 C109.1 IC13.1(OUTPUT) IC14.13(VCC2) R80.1 R89.1 R90.1 R164.2 TP27.1
+20V_Q1: C18.1 C19.1 C23.1 C24.1 IC3.1(OUTPUT) IC4.13(VCC2) R21.1 R30.1 R31.1 TP2.1
+20V_Q2: C38.1 C39.1 C43.1 C44.1 IC5.1(OUTPUT) IC6.13(VCC2) R32.1 R42.1 R43.1 TP7.1
+20V_Q3: C50.1 C51.1 C55.1 C56.1 IC7.1(OUTPUT) IC8.13(VCC2) R45.1 R54.1 R55.1 TP12.1
+20V_Q4: C70.1 C71.1 C75.1 C76.1 IC9.1(OUTPUT) IC10.13(VCC2) R57.1 R66.1 R67.1 TP17.1
+24V: C22.1 C42.1 C54.1 C74.1 C82.1 C102.1 PS2.1(+VIN) PS3.1(+VIN) PS4.1(+VIN) PS5.1(+VIN) PS6.1(+VIN) PS7.1(+VIN) ; also on sheet 1 3
GND: C25.2 C45.2 C57.2 C77.2 C87.2 C107.2 IC4.1(VS1) IC4.4(VS2) IC6.1(VS1) IC6.4(VS2) IC8.1(VS1) IC8.4(VS2) IC10.1(VS1) IC10.4(VS2) IC12.1(VS1) IC12.4(VS2) IC14.1(VS1) IC14.4(VS2) ; also on sheet 1 2 3 7
GND_24V: C22.2 C42.2 C54.2 C74.2 C82.2 C102.2 PS2.2(-VIN) PS3.2(-VIN) PS4.2(-VIN) PS5.2(-VIN) PS6.2(-VIN) PS7.2(-VIN) ; also on sheet 1 3
GND_Q1: C18.2 C20.2 C21.2 C24.2 C31.2 D12.A IC3.3(SHUTDOWN) IC3.4(GND) IC4.9(VEE1) IC4.12(VEE2) PS2.5(-VOUT) R22.2 R173.2 TP6.1
GND_Q2: C38.2 C40.2 C41.2 C44.2 C49.2 D18.A IC5.3(SHUTDOWN) IC5.4(GND) IC6.9(VEE1) IC6.12(VEE2) PS3.5(-VOUT) R33.2 R174.2 TP11.1
GND_Q3: C50.2 C52.2 C53.2 C56.2 C61.2 D24.A IC7.3(SHUTDOWN) IC7.4(GND) IC8.9(VEE1) IC8.12(VEE2) PS4.5(-VOUT) R46.2 R175.2 TP16.1
GND_Q4: C70.2 C72.2 C73.2 C76.2 C81.2 D30.A IC9.3(SHUTDOWN) IC9.4(GND) IC10.9(VEE1) IC10.12(VEE2) PS5.5(-VOUT) R58.2 R176.2 TP21.1
GND_Q5: C83.2 C84.2 C86.2 C88.2 C92.2 D36.A IC11.3(SHUTDOWN) IC11.4(GND) IC12.9(VEE1) IC12.12(VEE2) PS6.5(-VOUT) R70.2 R177.2 TP26.1
GND_Q6: C103.2 C104.2 C106.2 C108.2 C112.2 D42.A IC13.3(SHUTDOWN) IC13.4(GND) IC14.9(VEE1) IC14.12(VEE2) PS7.5(-VOUT) R82.2 R178.2 TP31.1
/FLT_OUT_HV: IC4.3(FLT) IC6.3(FLT) IC8.3(FLT) IC10.3(FLT) ; also on sheet 1
/FLT_OUT_LV: IC12.3(FLT) IC14.3(FLT) ; also on sheet 1 3
/PWM_2A: IC4.5(K1) IC4.8(K2) R28.2 ; also on sheet 1
/PWM_2B: IC6.5(K1) IC6.8(K2) R40.2 ; also on sheet 1
/PWM_3A: IC8.5(K1) IC8.8(K2) R52.2 ; also on sheet 1
/PWM_3B: IC10.5(K1) IC10.8(K2) R64.2 ; also on sheet 1
/PWM_5A: IC12.5(K1) IC12.8(K2) R75.2 ; also on sheet 1
/PWM_5B: IC14.5(K1) IC14.8(K2) R87.2 ; also on sheet 1
HV_DC_N: C34.2 C35.2 C36.2 C37.2 C43.2 C46.2 C47.2 C49.1 C66.2 C67.2 C68.2 C69.2 C75.2 C78.2 C79.2 C81.1 D16.A D17.A D18.K(C) D28.A D29.A D30.K(C) D60.A1 D60.A3 D62.A1 D62.A3 IC6.16(VE) IC10.16(VE) Q2.S Q4.S R41.2 R42.2 R43.2 R65.2 R66.2 R67.2 R174.1 R176.1 TP10.1 TP20.1 ; also on sheet 7
HV_DC_P: C28.1 C29.1 C32.1 C33.1 C62.1 C63.1 C64.1 C65.1 D7.K(C) D19.K(C) D59.K2 D61.K2 Q1.D Q3.D ; also on sheet 7
LV_DC_N: C98.2 C99.2 C100.2 C101.2 C109.2 C110.2 C111.2 C112.1 D40.A D41.A D42.K(C) D64.A1 D64.A3 IC14.16(VE) Q6.S R89.2 R90.2 R91.2 R178.1 TP30.1 ; also on sheet 2 3
LV_DC_P: C94.1 C95.1 C96.1 C97.1 D31.K(C) D63.K2 Q5.D ; also on sheet 2 3
SIG159: C28.2 C29.2 C32.2 C33.2 C34.1 C35.1 C36.1 C37.1
SIG249: C27.1 D10.K(C) D11.K(C) IC4.14(DESAT) R24.1 R25.1 TP3.1
SIG250: D8.A R24.2
SIG253: R20.1 R21.2
SIG256: C19.2 IC3.7(FEEDBACK) R20.2 R22.1
SIG257: D9.K(C) R26.1
SIG258: D7.A D8.K(C)
SIG263: IC4.6(A1) IC4.7(A2) R23.2 R28.1
SIG265: C26.1 D9.A IC4.10(Vclamp) Q1.G R27.2 R29.1 TP4.1
SIG267: C20.1 C21.1 IC3.8(INPUT) PS2.7(+VOUT)
SIG268: C23.2 C26.2 C27.2 C31.1 D10.A D11.A D12.K(C) D13.K(C) D59.A1 D59.A3 D60.K2 IC4.16(VE) Q1.S Q2.D R29.2 R30.2 R31.2 R173.1 TB3.1 TB3.2 TB3.3 TB3.4 TP5.1
SIG401: IC4.11(Vout) R25.2 R26.2 R27.1
SIG402: C39.2 IC5.7(FEEDBACK) R33.1 R34.2
SIG404: D14.A R36.2
SIG405: R32.2 R34.1
SIG407: C46.1 D15.A IC6.10(Vclamp) Q2.G R39.2 R41.1 TP9.1
SIG411: IC6.6(A1) IC6.7(A2) R35.2 R40.1
SIG413: C47.1 D16.K(C) D17.K(C) IC6.14(DESAT) R36.1 R37.1 TP8.1
SIG414: D15.K(C) R38.1
SIG415: D13.A D14.K(C)
SIG416: C40.1 C41.1 IC5.8(INPUT) PS3.7(+VOUT)
SIG417: IC6.11(Vout) R37.2 R38.2 R39.1
SIG418: C51.2 IC7.7(FEEDBACK) R44.2 R46.1
SIG422: D20.A R48.2
SIG424: R44.1 R45.2
SIG426: IC10.6(A1) IC10.7(A2) R59.2 R64.1
SIG428: C79.1 D28.K(C) D29.K(C) IC10.14(DESAT) R60.1 R61.1 TP18.1
SIG429: D25.A D26.K(C)
SIG435: C72.1 C73.1 IC9.8(INPUT) PS5.7(+VOUT)
SIG436: IC10.11(Vout) R61.2 R62.2 R63.1
SIG437: C58.1 D21.A IC8.10(Vclamp) Q3.G R51.2 R53.1 TP14.1
SIG439: D27.K(C) R62.1
SIG442: D26.A R60.2
SIG443: C78.1 D27.A IC10.10(Vclamp) Q4.G R63.2 R65.1 TP19.1
SIG444: R56.1 R57.2
SIG446: C71.2 IC9.7(FEEDBACK) R56.2 R58.1
SIG448: IC8.6(A1) IC8.7(A2) R47.2 R52.1
SIG452: C59.1 D22.K(C) D23.K(C) IC8.14(DESAT) R48.1 R49.1 TP13.1
SIG454: C55.2 C58.2 C59.2 C61.1 D22.A D23.A D24.K(C) D25.K(C) D61.A1 D61.A3 D62.K2 IC8.16(VE) Q3.S Q4.D R53.2 R54.2 R55.2 R175.1 TB4.1 TB4.2 TB4.3 TB4.4 TP15.1
SIG455: D21.K(C) R50.1
SIG456: C62.2 C63.2 C64.2 C65.2 C66.1 C67.1 C68.1 C69.1
SIG459: D19.A D20.K(C)
SIG460: C52.1 C53.1 IC7.8(INPUT) PS4.7(+VOUT)
SIG462: IC8.11(Vout) R49.2 R50.2 R51.1
SIG464: IC14.6(A1) IC14.7(A2) R83.2 R87.1
SIG466: C103.1 C104.1 IC13.8(INPUT) R164.1 R165.2 R166.2
SIG470: C105.2 IC13.7(FEEDBACK) R81.2 R82.1
SIG471: PS7.7(+VOUT) R165.1
SIG472: PS7.6(0V) R166.1
SIG473: IC14.11(Vout) R85.2 R86.2 R88.2
SIG474: D37.A R84.1
SIG476: C111.1 D39.A IC14.10(Vclamp) Q6.G R88.1 R91.1 TP29.1
SIG477: C110.1 D40.K(C) D41.K(C) IC14.14(DESAT) R84.2 R85.1 TP28.1
SIG478: D39.K(C) R86.1
SIG479: R80.2 R81.1
N17112878: C83.1 C84.1 IC11.8(INPUT) R161.1 R162.2 R163.2
N17112898: C85.2 IC11.7(FEEDBACK) R69.2 R70.1
N17112910: R68.2 R69.1
N17113118: C89.2 C90.2 C91.2 C92.1 D34.A D35.A D36.K(C) D37.K(C) D63.A1 D63.A3 D64.K2 IC12.16(VE) Q5.S Q6.D R77.2 R78.2 R79.2 R177.1 TB5.1 TB5.2 TB5.3 TB5.4 TP25.1
N17113144: IC12.6(A1) IC12.7(A2) R71.2 R75.1
N17113163: C90.1 D34.K(C) D35.K(C) IC12.14(DESAT) R72.2 R73.1 TP23.1
N17113169: D31.A R72.1
N17113250: IC12.11(Vout) R73.2 R74.2 R76.2
N17113252: D33.K(C) R74.1
N17113254: C91.1 D33.A IC12.10(Vclamp) Q5.G R76.1 R79.1 TP24.1
N17113532: C94.2 C95.2 C96.2 C97.2 C98.1 C99.1 C100.1 C101.1
N17391340: PS6.7(+VOUT) R162.1
N17392773: PS6.6(0V) R163.1

Not connected (* = marked no-connect by the designer): IC3 2(SENSE) 5(ERROR) 6(VTAP); IC4 15(Vled); IC5 2(SENSE) 5(ERROR) 6(VTAP); IC6 15(Vled); IC7 2(SENSE) 5(ERROR) 6(VTAP); IC8 15(Vled); IC9 2(SENSE) 5(ERROR) 6(VTAP); IC10 15(Vled); IC11 2(SENSE) 5(ERROR) 6(VTAP); IC12 15(Vled); IC13 2(SENSE) 5(ERROR) 6(VTAP); IC14 15(Vled); PS2 6(0V); PS3 6(0V); PS4 6(0V); PS5 6(0V)

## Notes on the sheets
sheet 4
- 1608
- 2012
- 1608
- 3216
- 1608
- 1608
- 3216
- 1608
- 1608
- 1608
- 1608
- 1608
- 1608
- 1608
- 6432
- 1608
- 6432
- 1608
- 1608
- 1608
- 1608
- 2012
- L+
- 2012
- 1608
- 2012
- 3216
- 1608
- 1608
- 1608
- 3216
- 1608
- 1608
- 1608
- 1608
- 1608
- 1608
- 1608
- 6432
- 1608
- 6432
- 1608
- 1608
- 1608
- 1608
- 2012
- 2012
sheet 5
- 1608
- 1608
- 1608
- 3216
- 1608
- 1608
- 3216
- 1608
- 1608
- 1608
- 1608
- 1608
- 6432
- 1608
- 6432
- 1608
- 1608
- 1608
- 1608
- 2012
- 2012
- Tr+
- 1608
- 1608
- 3216
- 1608
- 1608
- 3216
- 1608
- 1608
- 1608
- 1608
- 1608
- 1608
- 6432
- 1608
- 6432
- 1608
- 1608
- 1608
- 1608
- 2012
- 2012
sheet 6
- 1608
- 1608
- 1608
- 3216
- 1608
- 1608
- 3216
- 1608
- 1608
- 1608
- 1608
- 1608
- 6432
- 6432
- 1608
- 1608
- 1608
- 1608
- 1608
- 2012
- 2012
- Tr+
- 1608
- 1608
- 3216
- 1608
- 1608
- 1608
- 3216
- 1608
- 1608
- 1608
- 1608
- 1608
- 6432
- 1608
- 6432
- 1608
- 1608
- 1608
- 1608
- 2012
- 2012
